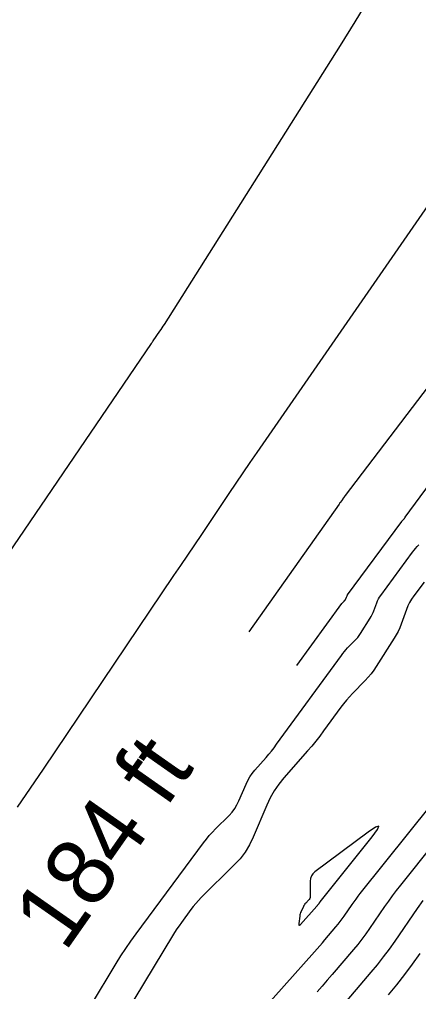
# Model space of a CAD drawing. Extents: x 7585033 to 7595090, y 547091 to 553471.
# Drawn here: x 7587101.7 to 7587138.9, y 547796.5 to 547887 of the extents above; entities that cross this region are included whole.
import ezdxf

# ---------------------------------------------------------------- set-up
doc = ezdxf.new("R2010")
doc.units = 0
for name, color, linetype in [('E_TERR_DSPLAY_GeneralTx', 7, 'Continuous'), ('E_TERR_DSPLAY_MajContour', 7, 'Continuous'), ('E_TERR_DSPLAY_MinContour', 7, 'Continuous')]:
    doc.layers.add(name, color=color, linetype=linetype)

msp = doc.modelspace()

# ---------------------------------------------------------------- linework, layer by layer
at = {"layer": 'E_TERR_DSPLAY_MajContour'}
for points in [[(7587155.921, 547873.988), (7587132.036, 547842.643), (7587132.016, 547842.617), (7587131.997, 547842.591), (7587131.978, 547842.564), (7587131.96, 547842.537), (7587131.877, 547842.413), (7587131.864, 547842.393), (7587131.85, 547842.374), (7587131.837, 547842.354), (7587131.823, 547842.334), (7587131.769, 547842.255), (7587131.755, 547842.235), (7587131.741, 547842.215), (7587131.727, 547842.196), (7587131.713, 547842.177), (7587131.577, 547841.997), (7587131.55, 547841.961), (7587131.523, 547841.924), (7587131.496, 547841.887), (7587131.47, 547841.85), (7587123.046, 547829.96)], [(7587136.069, 547796.144), (7587136.844, 547797.076), (7587137.593, 547798.028), (7587138.318, 547798.999), (7587139.017, 547799.99)]]:
    msp.add_lwpolyline(points, dxfattribs=at)
msp.add_lwpolyline([(7587128.764, 547805.199), (7587128.737, 547805.113), (7587128.694, 547805.034), (7587128.634, 547804.962), (7587128.358, 547804.689), (7587128.292, 547804.619), (7587128.234, 547804.543), (7587128.183, 547804.462), (7587128.139, 547804.376), (7587127.928, 547803.915), (7587127.884, 547803.808), (7587127.848, 547803.698), (7587127.821, 547803.586), (7587127.802, 547803.471), (7587127.716, 547802.787), (7587127.711, 547802.668), (7587127.738, 547802.616), (7587127.794, 547802.631), (7587127.882, 547802.712), (7587129.395, 547804.408), (7587129.414, 547804.429), (7587129.432, 547804.45), (7587129.45, 547804.47), (7587129.468, 547804.491), (7587129.544, 547804.581), (7587129.559, 547804.599), (7587129.574, 547804.618), (7587129.588, 547804.637), (7587129.602, 547804.656), (7587129.656, 547804.735), (7587129.67, 547804.755), (7587129.684, 547804.774), (7587129.698, 547804.793), (7587129.713, 547804.812), (7587134.565, 547810.875), (7587135.064, 547811.556), (7587135.164, 547811.851), (7587134.866, 547811.761), (7587134.169, 547811.285), (7587129.224, 547807.598), (7587129.033, 547807.421), (7587128.896, 547807.218), (7587128.813, 547806.987), (7587128.784, 547806.729), (7587128.773, 547805.293)], close=True, dxfattribs=at)
at = {"layer": 'E_TERR_DSPLAY_MinContour'}
for points in [[(7587095.969, 547830.371), (7587113.986, 547856.812), (7587113.999, 547856.831), (7587114.012, 547856.85), (7587114.025, 547856.87), (7587114.037, 547856.889), (7587114.088, 547856.967), (7587114.1, 547856.986), (7587114.113, 547857.006), (7587114.126, 547857.025), (7587114.139, 547857.044), (7587114.771, 547857.943), (7587114.879, 547858.099), (7587114.986, 547858.258), (7587115.091, 547858.417), (7587115.194, 547858.578), (7587131.604, 547884.556), (7587132.952, 547886.735), (7587134.262, 547888.936)], [(7587143.371, 547874.888), (7587123.813, 547846.654), (7587123.158, 547845.704), (7587122.505, 547844.751), (7587121.856, 547843.797), (7587121.21, 547842.84), (7587118.633, 547839.009), (7587117.989, 547838.052), (7587117.344, 547837.094), (7587116.699, 547836.137), (7587116.053, 547835.18), (7587103.894, 547817.155), (7587102.693, 547815.385), (7587101.481, 547813.622)], [(7587127.528, 547826.82), (7587131.736, 547832.587), (7587131.755, 547832.613), (7587131.776, 547832.638), (7587131.798, 547832.663), (7587131.82, 547832.687), (7587131.912, 547832.78), (7587131.934, 547832.804), (7587131.955, 547832.829), (7587131.974, 547832.855), (7587131.993, 547832.882), (7587132.123, 547833.086), (7587132.137, 547833.11), (7587132.15, 547833.135), (7587132.162, 547833.161), (7587132.172, 547833.187), (7587132.211, 547833.293), (7587132.221, 547833.319), (7587132.234, 547833.344), (7587132.248, 547833.368), (7587132.264, 547833.392), (7587137.303, 547840.222), (7587137.313, 547840.235), (7587137.323, 547840.248), (7587137.334, 547840.261), (7587137.345, 547840.273), (7587137.391, 547840.321), (7587137.402, 547840.333), (7587137.413, 547840.346), (7587137.424, 547840.358), (7587137.435, 547840.371), (7587137.552, 547840.508), (7587137.575, 547840.536), (7587137.597, 547840.563), (7587137.619, 547840.592), (7587137.64, 547840.62), (7587139.996, 547843.831)], [(7587108.302, 547795.085), (7587110.696, 547799.056), (7587111.137, 547799.768), (7587111.595, 547800.47), (7587112.069, 547801.16), (7587112.56, 547801.84), (7587118.836, 547810.315), (7587119.099, 547810.657), (7587119.375, 547810.988), (7587119.664, 547811.308), (7587119.965, 547811.617), (7587121.222, 547812.86), (7587121.499, 547813.161), (7587121.743, 547813.485), (7587121.954, 547813.831), (7587122.133, 547814.199), (7587122.799, 547815.752), (7587122.967, 547816.105), (7587123.16, 547816.442), (7587123.38, 547816.762), (7587123.626, 547817.066), (7587124.661, 547818.25), (7587124.916, 547818.548), (7587125.165, 547818.852), (7587125.407, 547819.162), (7587125.642, 547819.476), (7587131.681, 547827.754), (7587131.818, 547827.936), (7587131.962, 547828.111), (7587132.111, 547828.282), (7587132.267, 547828.447), (7587132.903, 547829.097), (7587133.058, 547829.264), (7587133.203, 547829.437), (7587133.339, 547829.618), (7587133.466, 547829.806), (7587134.369, 547831.22), (7587134.469, 547831.388), (7587134.56, 547831.561), (7587134.642, 547831.738), (7587134.713, 547831.92), (7587134.981, 547832.657), (7587135.054, 547832.838), (7587135.139, 547833.012), (7587135.237, 547833.18), (7587135.347, 547833.341), (7587138.321, 547837.372), (7587138.456, 547837.549), (7587138.595, 547837.721), (7587138.74, 547837.89), (7587138.89, 547838.054)], [(7587139.385, 547834.584), (7587138.431, 547833.291), (7587138.226, 547832.992), (7587138.045, 547832.68), (7587137.886, 547832.357), (7587137.751, 547832.021), (7587137.254, 547830.652), (7587137.121, 547830.315), (7587136.97, 547829.986), (7587136.801, 547829.666), (7587136.615, 547829.355), (7587134.939, 547826.729), (7587134.704, 547826.38), (7587134.451, 547826.045), (7587134.182, 547825.723), (7587133.895, 547825.414), (7587132.715, 547824.207), (7587132.425, 547823.901), (7587132.148, 547823.584), (7587131.881, 547823.258), (7587131.627, 547822.922), (7587130.021, 547820.722), (7587129.666, 547820.245), (7587129.3, 547819.777), (7587128.924, 547819.317), (7587128.538, 547818.866), (7587126.331, 547816.343), (7587125.858, 547815.757), (7587125.435, 547815.14), (7587125.062, 547814.492), (7587124.739, 547813.812), (7587123.458, 547810.822), (7587123.113, 547810.113), (7587122.706, 547809.447), (7587122.236, 547808.824), (7587121.702, 547808.244), (7587118.628, 547805.204), (7587118.369, 547804.938), (7587118.121, 547804.662), (7587117.884, 547804.378), (7587117.657, 547804.083), (7587116.772, 547802.888), (7587116.554, 547802.587), (7587116.344, 547802.28), (7587116.141, 547801.969), (7587115.945, 547801.653), (7587110.649, 547792.869)], [(7587112.225, 547781.157), (7587129.175, 547800.153), (7587129.421, 547800.43), (7587129.665, 547800.708), (7587129.908, 547800.988), (7587130.149, 547801.269), (7587131.175, 547802.472), (7587131.381, 547802.718), (7587131.579, 547802.97), (7587131.771, 547803.228), (7587131.956, 547803.49), (7587132.683, 547804.549), (7587132.867, 547804.812), (7587133.056, 547805.072), (7587133.25, 547805.328), (7587133.448, 547805.58), (7587142.371, 547816.733)], [(7587143.719, 547814.518), (7587137.183, 547806.349), (7587136.801, 547805.862), (7587136.428, 547805.369), (7587136.064, 547804.869), (7587135.71, 547804.363), (7587134.31, 547802.323), (7587133.953, 547801.818), (7587133.584, 547801.323), (7587133.202, 547800.838), (7587132.807, 547800.362), (7587130.831, 547798.047), (7587130.366, 547797.506), (7587129.899, 547796.967), (7587129.428, 547796.431)], [(7587139.261, 547804.927), (7587138.736, 547804.177), (7587136.663, 547801.156), (7587136.135, 547800.409), (7587135.589, 547799.676), (7587135.023, 547798.957), (7587134.438, 547798.253), (7587131.513, 547794.825)]]:
    msp.add_lwpolyline(points, dxfattribs=at)

# ---------------------------------------------------------------- texts
at = {"layer": 'E_TERR_DSPLAY_GeneralTx'}
msp.add_text('184 ft', height=6.3, rotation=54.97835, dxfattribs=at).set_placement((7587105.92, 547800.032))

doc.saveas('drawing.dxf')
